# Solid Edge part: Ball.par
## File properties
Author: jmrobins
Template: NORMMET.PAR
Last saved by: rkriggs
Revision: 52
Application: Solid Edge
Density: 0.0000088 kg/mm^3
Accuracy: 0.99
Material: Bronze, 90%
Face Style: Bronze
Fill Style: ANSI33(Brass)
Virtual Style: Brushed bronze
Coef. of Thermal Exp: 1.8e-05
Thermal Conductivity: 189.0
Specific Heat: 377.0
Modulus of Elasticity: 117210869000.0
Poission's Ratio: 0.36
Yield Stress: 372316878.0
Ultimate Stress: 420580177.0
Elongation: 0.0
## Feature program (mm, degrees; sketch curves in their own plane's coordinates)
pattern "PatternOccurrence_1"
pattern "unnamed Pattern 1"
pattern "unnamed Pattern 2"
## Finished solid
Body 1: solid body, 11 faces, 22 edges, 8 vertices.
  Faces by surface: cylinder 7, plane 3, sphere 1
  Edges by curve: circle 12, line 6, intersection 4
Bounding box of the edges (mm; curved faces can reach further): 60.000 x 25.981 x 59.580, from (-30, 3.7054, -30) to (30, 29.6862, 29.5804).
Cylindrical faces by radius (mm): R1.5 x4, R7.5 x2, R15 x1
Spherical faces by radius (mm): R30 x1
Planar faces by outward normal: +z 1, -y 2
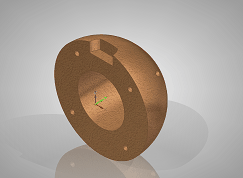
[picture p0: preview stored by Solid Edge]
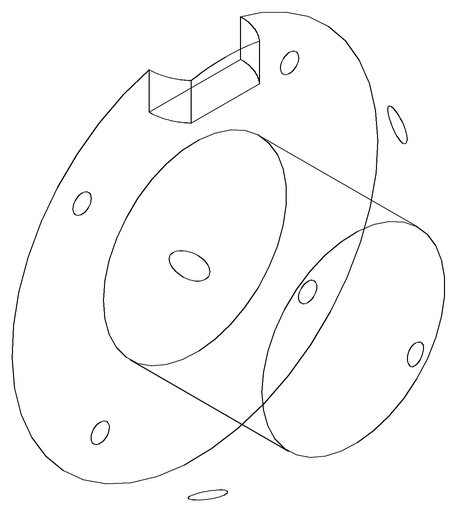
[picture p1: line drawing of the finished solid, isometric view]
